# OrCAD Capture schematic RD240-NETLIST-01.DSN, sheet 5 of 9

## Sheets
5 5: size A3
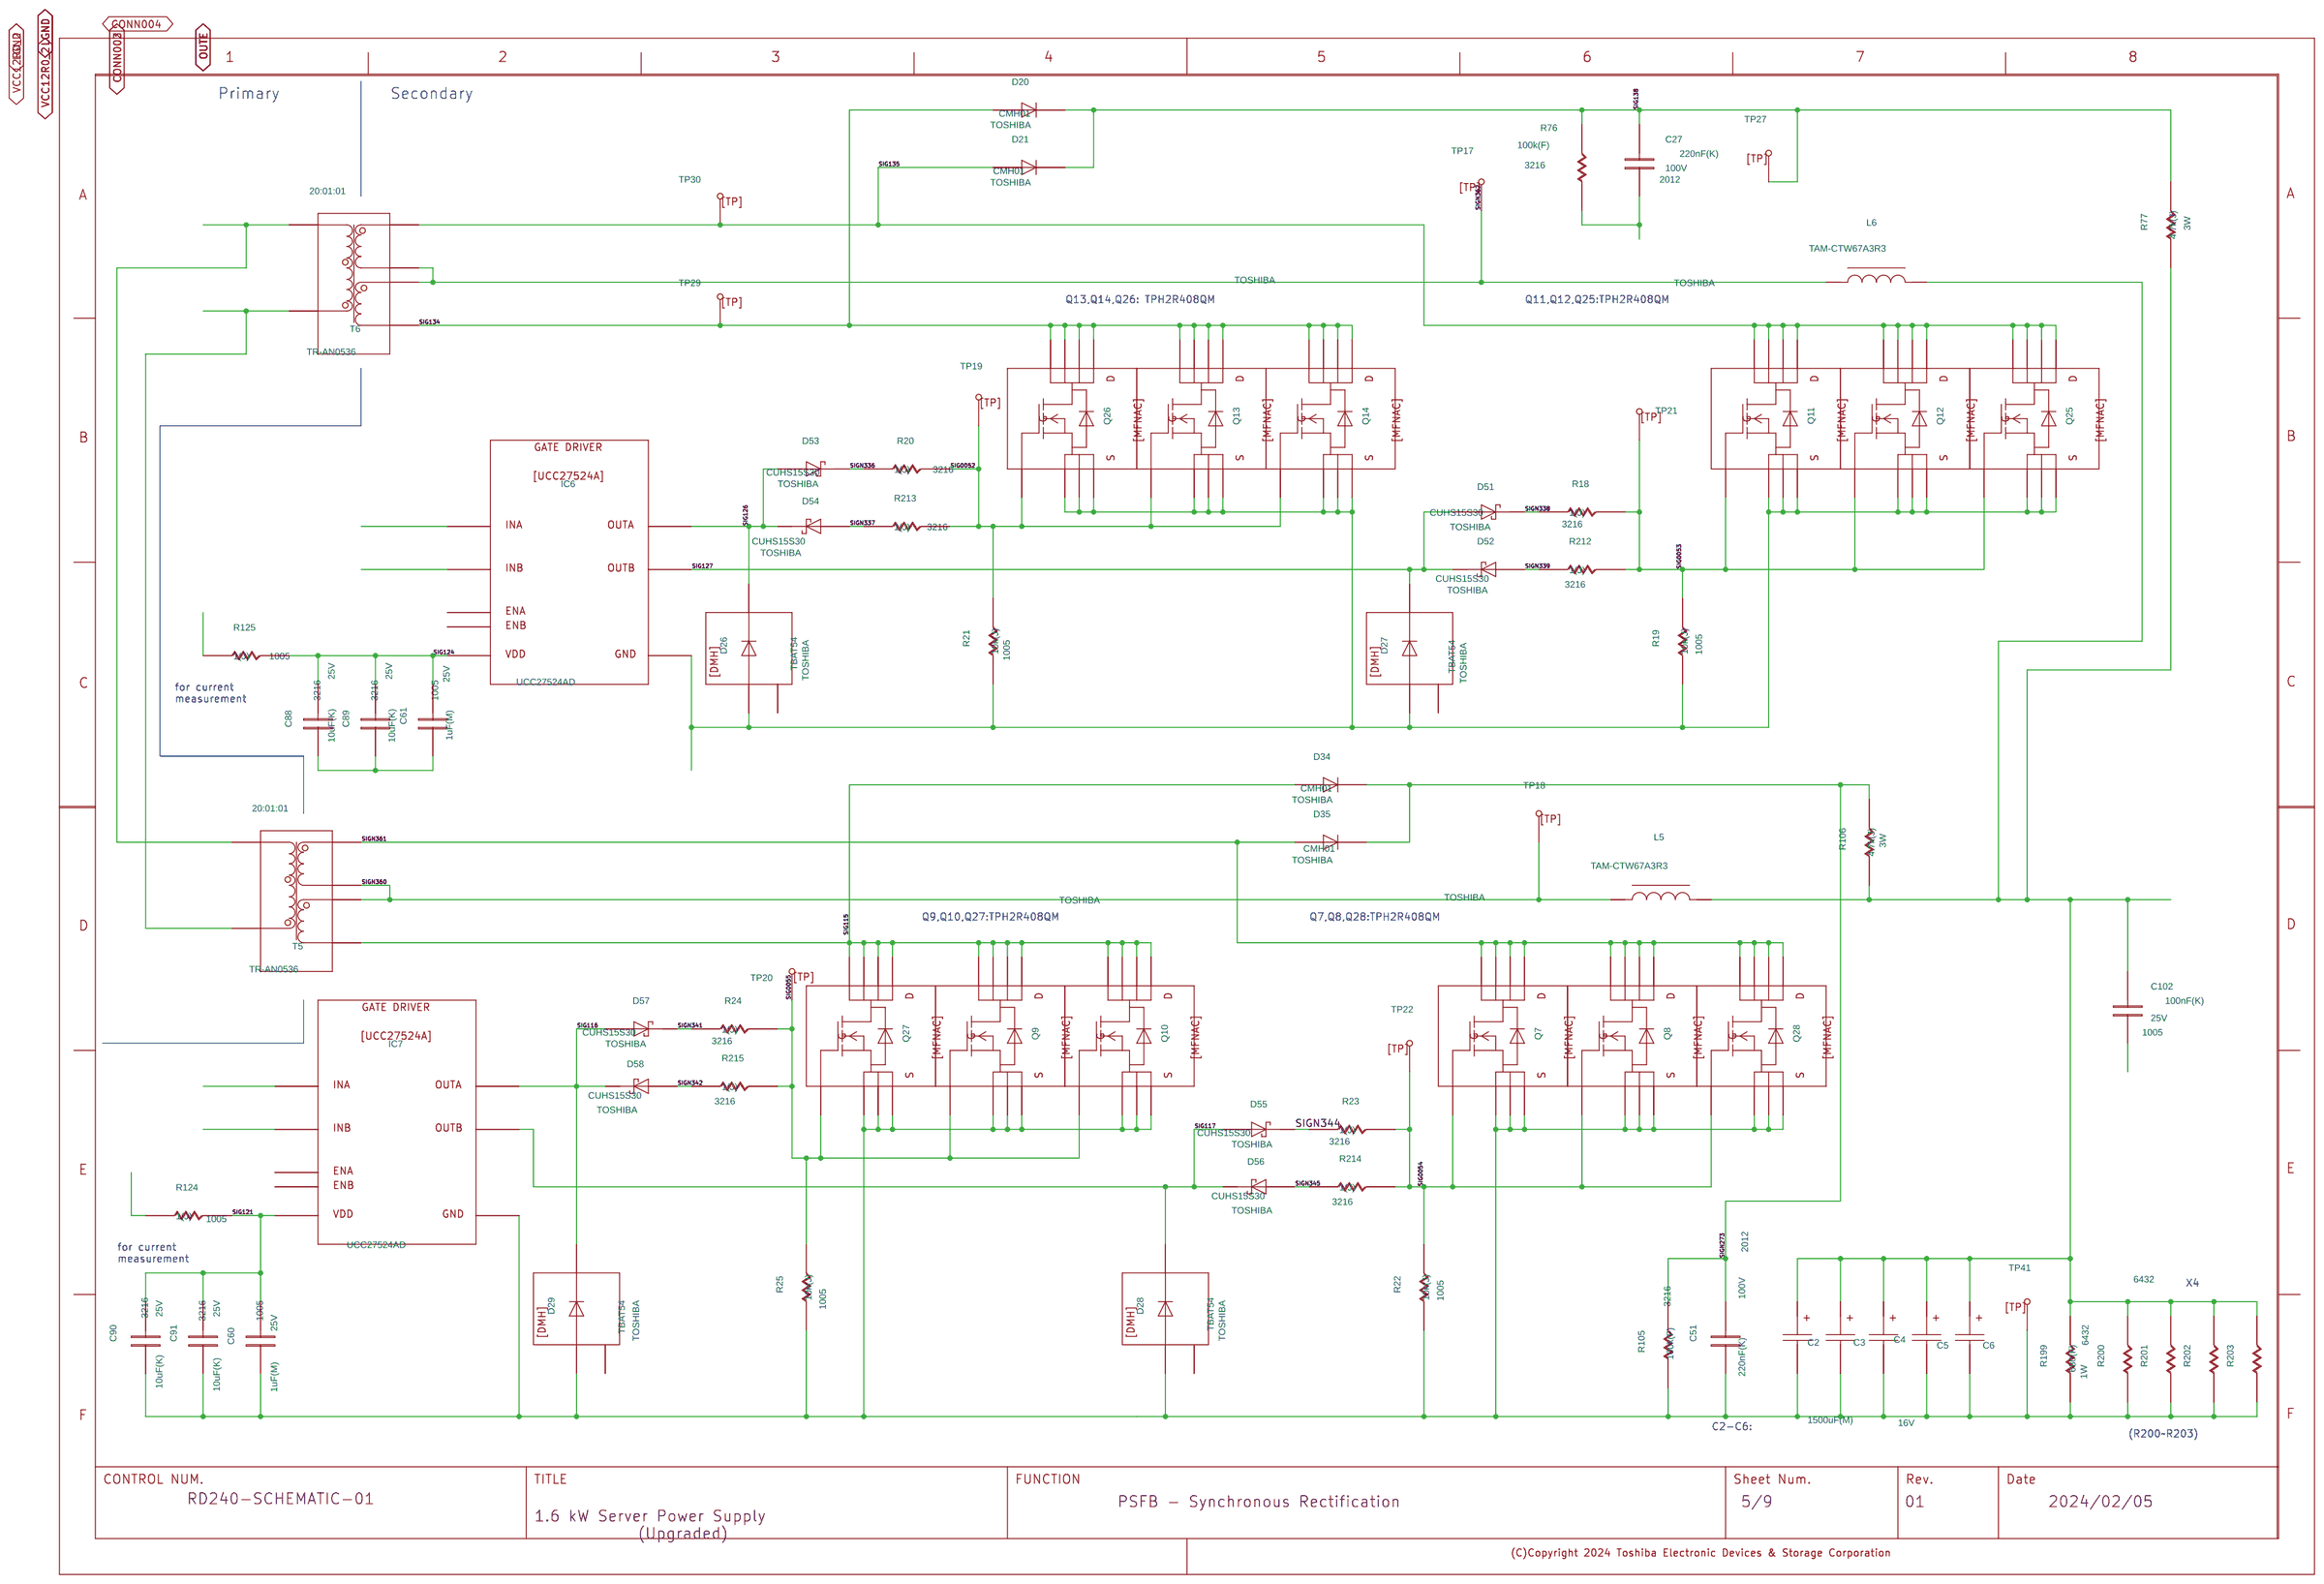
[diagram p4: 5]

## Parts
C2  CP
C3  CP
C4  CP
C5  CP
C6  CP
C27  C
C51  C
C60  C
C61  C
C88  C
C89  C
C90  C
C91  C
C102  C
D20  D
D21  D
D26  DMH
D27  DMH
D28  DMH
D29  DMH
D34  D
D35  D
D51  CUHS15S30
D52  CUHS15S30
D53  CUHS15S30
D54  CUHS15S30
D55  CUHS15S30
D56  CUHS15S30
D57  CUHS15S30
D58  CUHS15S30
IC6  L27524
IC7  L27524
L5  CTW_67A3_3UH
L6  CTW_67A3_3UH
Q7  TPH2R408QM_8PIN
Q8  TPH2R408QM_8PIN
Q9  TPH2R408QM_8PIN
Q10  TPH2R408QM_8PIN
Q11  TPH2R408QM_8PIN
Q12  TPH2R408QM_8PIN
Q13  TPH2R408QM_8PIN
Q14  TPH2R408QM_8PIN
Q25  TPH2R408QM_8PIN
Q26  TPH2R408QM_8PIN
Q27  TPH2R408QM_8PIN
Q28  TPH2R408QM_8PIN
R18  R
R19  R
R20  R
R21  R
R22  R
R23  R
R24  R
R25  R
R76  R
R77  R
R105  R
R106  R
R124  R
R125  R
R199  R
R200  R
R201  R
R202  R
R203  R
R212  R
R213  R
R214  R
R215  R
T5  T3_12V67A
T6  T3_12V67A
TP17  TP
TP18  TP
TP19  TP
TP20  TP
TP21  TP
TP22  TP
TP27  TP
TP29  TP
TP30  TP
TP41  TP
U?#4  WAKU_DEF100

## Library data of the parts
C2 = CP: AUTHOR: sptcae13; CAPACITANCETOLE: M; CDMASTERCADCELG: DC0341; CHIPSIZE: D10xL22; COMP: PRT_3; COMPONENTTYPE: 4; DATE: 2024/01/31; FNLEADFREETHET1GT2GMCTH1: 0_2_N; GCOUNT: 1; INSTANCENAME: cmp31; MAKER: RUBYCON; MAXGCOUNT: 1; NOMINALCAPACITA: 56u; OUMECLASSIFICATION: ƒAƒ‹ƒ~“d‰ðƒRƒ“ƒfƒ“ƒT; OUMEPARTTYPE: C; PMPRODUCTSTYPEG: SV1; QUADMODEL: CON_56U; RATEDVOLTAGE: 16; SIZECODESMD: DIP; TIME: 13:58:24; UPDATEDATE: 2024/01/31; UPDATETIME: 13:58:24; UPDATEUSER: sptcae13; VAL1: 1500uF(M); VAL2: 16V; VAL3: ELXZ160ELL152MJ30S
C3 = CP: AUTHOR: sptcae13; CAPACITANCETOLE: M; CHIPSIZE: D10xL22; COMP: PRT_3; COMPONENTTYPE: 4; DATE: 2024/01/31; GCOUNT: 1; INSTANCENAME: cmp32; MAKER: RUBYCON; MAXGCOUNT: 1; NOMINALCAPACITA: 56u; PMPRODUCTSTYPEG: SV1; RATEDVOLTAGE: 16; SIZECODESMD: DIP; TIME: 13:58:24; UPDATEDATE: 2024/01/31; UPDATETIME: 13:58:24; UPDATEUSER: sptcae13; VAL1: 1500uF(M); VAL2: 16V; VAL3: ELXZ160ELL152MJ30S
C4 = CP: AUTHOR: sptcae13; CAPACITANCETOLE: M; CHIPSIZE: D10xL22; COMP: PRT_3; COMPONENTTYPE: 4; DATE: 2024/01/31; GCOUNT: 1; INSTANCENAME: cmp33; MAKER: RUBYCON; MAXGCOUNT: 1; NOMINALCAPACITA: 56u; PMPRODUCTSTYPEG: SV1; RATEDVOLTAGE: 16; SIZECODESMD: DIP; TIME: 13:58:24; UPDATEDATE: 2024/01/31; UPDATETIME: 13:58:24; UPDATEUSER: sptcae13; VAL1: 1500uF(M); VAL2: 16V; VAL3: ELXZ160ELL152MJ30S
C5 = CP: AUTHOR: sptcae13; CAPACITANCETOLE: M; CHIPSIZE: D10xL22; COMP: PRT_3; COMPONENTTYPE: 4; DATE: 2024/01/31; GCOUNT: 1; INSTANCENAME: cmp34; MAKER: RUBYCON; MAXGCOUNT: 1; NOMINALCAPACITA: 56u; PMPRODUCTSTYPEG: SV1; RATEDVOLTAGE: 16; SIZECODESMD: DIP; TIME: 13:58:24; UPDATEDATE: 2024/01/31; UPDATETIME: 13:58:24; UPDATEUSER: sptcae13; VAL1: 1500uF(M); VAL2: 16V; VAL3: ELXZ160ELL152MJ30S
C6 = CP: AUTHOR: sptcae13; CAPACITANCETOLE: M; CHIPSIZE: D10xL22; COMP: PRT_3; COMPONENTTYPE: 4; DATE: 2024/01/31; GCOUNT: 1; INSTANCENAME: cmp35; MAKER: RUBYCON; MAXGCOUNT: 1; NOMINALCAPACITA: 56u; PMPRODUCTSTYPEG: SV1; RATEDVOLTAGE: 16; SIZECODESMD: DIP; TIME: 13:58:24; UPDATEDATE: 2024/01/31; UPDATETIME: 13:58:24; UPDATEUSER: sptcae13; VAL1: 1500uF(M); VAL2: 16V; VAL3: ELXZ160ELL152MJ30S
C27 = C: ADSCNVFLAG: ON; ADSCOMPONENTNAME: C_2012; ADSMODELNAME: s_GRM21AR72A224KAC5L; ALLGREEN: N:¢²¸; AUTHOR: sptcae13; CAPACITANCETOLE: K; CHIPSIZE: 1005; COMP: K0302287; COMPONENTTYPE: 4; DATE: 2024/01/31; FNAPPROVALRESUG: 5:bè(KR[h); FNCANCELLATIONG: 0:Žg—p‰Â; FNENVIRONMANTRG: N:¢²¸; FNLEADFREETHET1GT2GMCTH1: N_N_N; FUNCN: K0302287; GCOUNT: 1; ICX_PART_MODEL: CON_220N; INSTANCENAME: cmp239; MAKER: TDK; MAXGCOUNT: 1; NOMINALCAPACITA: 220n; OUMECLASSIFICATION: ƒZƒ‰ƒ~ƒbƒNƒRƒ“ƒfƒ“ƒT; OUMEMAKER: MRT ºc»ì; OUMEMAKERKATAMEI: GRM21AR72A224KAC5L; QUADMODEL: CON_220N; RATEDVOLTAGE: 100; SAVECOUNT: 0; SIZECODESMD: 2012; SQ_PART_MODEL: CON_220N; TIME: 13:58:26; UPDATEDATE: 2024/01/31; UPDATETIME: 13:58:26; UPDATEUSER: sptcae13; VAL1: 220nF(K); VAL2: 100V; VAL3: GRM21AR72A224KAC5L
C51 = C: ADSCNVFLAG: ON; ADSCOMPONENTNAME: C_2012; ADSMODELNAME: s_GRM21AR72A224KAC5L; ALLGREEN: N:¢²¸; AUTHOR: sptcae13; CAPACITANCETOLE: K; CHIPSIZE: 1005; COMP: K0302287; COMPONENTTYPE: 4; DATE: 2024/01/31; FNAPPROVALRESUG: 5:bè(KR[h); FNCANCELLATIONG: 0:Žg—p‰Â; FNENVIRONMANTRG: N:¢²¸; FNLEADFREETHET1GT2GMCTH1: N_N_N; FUNCN: K0302287; GCOUNT: 1; ICX_PART_MODEL: CON_220N; INSTANCENAME: cmp240; MAKER: TDK; MAXGCOUNT: 1; NOMINALCAPACITA: 220n; OUMECLASSIFICATION: ƒZƒ‰ƒ~ƒbƒNƒRƒ“ƒfƒ“ƒT; OUMEMAKER: MRT ºc»ì; OUMEMAKERKATAMEI: GRM21AR72A224KAC5L; QUADMODEL: CON_220N; RATEDVOLTAGE: 100; SAVECOUNT: 0; SIZECODESMD: 2012; SQ_PART_MODEL: CON_220N; TIME: 13:58:26; UPDATEDATE: 2024/01/31; UPDATETIME: 13:58:26; UPDATEUSER: sptcae13; VAL1: 220nF(K); VAL2: 100V; VAL3: GRM21AR72A224KAC5L
C60 = C: ADSMODELNAME: s_GRM155B31E105KA12D; AUTHOR: sptcae13; CAPACITANCETOLE: K; CDMASTERCADCELG: KC0005; CHIPSIZE: 1005; COMP: PRT_52; COMPONENTTYPE: 4; DATE: 2024/01/31; FNLEADFREETHET1GT2GMCTH1: 3_0_N; GCOUNT: 1; INSTANCENAME: cmp226; MAKER: TDK; MAXGCOUNT: 1; NOMINALCAPACITA: 1u; OUMECLASSIFICATION: ƒZƒ‰ƒ~ƒbƒNƒRƒ“ƒfƒ“ƒT; OUMEMAKER: MRT ºc»ì; OUMEMAKERKATAMEI: GRM155B31E105KA12D; PMPRODUCTSTYPEG: HD1; QUADMODEL: CON_1U; RATEDVOLTAGE: 25; SAVECOUNT: 0; SIZECODESMD: 1005; TEMPCHARACTERI2: B; TIME: 13:58:26; UPDATEDATE: 2024/01/31; UPDATETIME: 13:58:26; UPDATEUSER: sptcae13; VAL1: 1uF(M); VAL2: 25V; VAL3: C1005X5R1E105M050BC
C61 = C: ADSMODELNAME: s_GRM155B31E105KA12D; AUTHOR: sptcae13; CAPACITANCETOLE: K; CDMASTERCADCELG: KC0005; CHIPSIZE: 1005; COMP: PRT_52; COMPONENTTYPE: 4; DATE: 2024/01/31; FNLEADFREETHET1GT2GMCTH1: 3_0_N; GCOUNT: 1; INSTANCENAME: cmp214; MAKER: TDK; MAXGCOUNT: 1; NOMINALCAPACITA: 1u; OUMECLASSIFICATION: ƒZƒ‰ƒ~ƒbƒNƒRƒ“ƒfƒ“ƒT; OUMEMAKER: MRT ºc»ì; OUMEMAKERKATAMEI: GRM155B31E105KA12D; PMPRODUCTSTYPEG: HD1; QUADMODEL: CON_1U; RATEDVOLTAGE: 25; SAVECOUNT: 0; SIZECODESMD: 1005; TEMPCHARACTERI2: B; TIME: 13:58:26; UPDATEDATE: 2024/01/31; UPDATETIME: 13:58:26; UPDATEUSER: sptcae13; VAL1: 1uF(M); VAL2: 25V; VAL3: C1005X5R1E105M050BC
C88 = C: ADSMODELNAME: s_TMK316LD106KL_T; AUTHOR: sptcae13; CAPACITANCETOLE: K; CDMASTERCADCELG: KC0014; CHIPSIZE: 3216; COMP: PRT_46; COMPONENTTYPE: 4; DATE: 2024/01/31; FNLEADFREETHET1GT2GMCTH1: N_N_N; GCOUNT: 1; INSTANCENAME: cmp213; MAKER: TAIYO YUDEN; MAXGCOUNT: 1; NOMINALCAPACITA: 10u; OUMECLASSIFICATION: ƒZƒ‰ƒ~ƒbƒNƒRƒ“ƒfƒ“ƒT; OUMEMAKER: TYD ‘¾—z—U“d; OUMEMAKERKATAMEI: TMK316LD106KL-T; QUADMODEL: CON_10U; RATEDVOLTAGE: 25; SAVECOUNT: 0; SIZECODESMD: 3216; TIME: 13:58:26; UPDATEDATE: 2024/01/31; UPDATETIME: 13:58:26; UPDATEUSER: sptcae13; VAL1: 10uF(K); VAL2: 25V; VAL3: TMK316BJ106KL-T
C89 = C: ADSMODELNAME: s_TMK316LD106KL_T; AUTHOR: sptcae13; CAPACITANCETOLE: K; CDMASTERCADCELG: KC0014; CHIPSIZE: 3216; COMP: PRT_46; COMPONENTTYPE: 4; DATE: 2024/01/31; FNLEADFREETHET1GT2GMCTH1: N_N_N; GCOUNT: 1; INSTANCENAME: cmp212; MAKER: TAIYO YUDEN; MAXGCOUNT: 1; NOMINALCAPACITA: 10u; OUMECLASSIFICATION: ƒZƒ‰ƒ~ƒbƒNƒRƒ“ƒfƒ“ƒT; OUMEMAKER: TYD ‘¾—z—U“d; OUMEMAKERKATAMEI: TMK316LD106KL-T; QUADMODEL: CON_10U; RATEDVOLTAGE: 25; SAVECOUNT: 0; SIZECODESMD: 3216; TIME: 13:58:26; UPDATEDATE: 2024/01/31; UPDATETIME: 13:58:26; UPDATEUSER: sptcae13; VAL1: 10uF(K); VAL2: 25V; VAL3: TMK316BJ106KL-T
C90 = C: ADSMODELNAME: s_TMK316LD106KL_T; AUTHOR: sptcae13; CAPACITANCETOLE: K; CDMASTERCADCELG: KC0014; CHIPSIZE: 3216; COMP: PRT_46; COMPONENTTYPE: 4; DATE: 2024/01/31; FNLEADFREETHET1GT2GMCTH1: N_N_N; GCOUNT: 1; INSTANCENAME: cmp224; MAKER: TAIYO YUDEN; MAXGCOUNT: 1; NOMINALCAPACITA: 10u; OUMECLASSIFICATION: ƒZƒ‰ƒ~ƒbƒNƒRƒ“ƒfƒ“ƒT; OUMEMAKER: TYD ‘¾—z—U“d; OUMEMAKERKATAMEI: TMK316LD106KL-T; QUADMODEL: CON_10U; RATEDVOLTAGE: 25; SAVECOUNT: 0; SIZECODESMD: 3216; TIME: 13:58:26; UPDATEDATE: 2024/01/31; UPDATETIME: 13:58:26; UPDATEUSER: sptcae13; VAL1: 10uF(K); VAL2: 25V; VAL3: TMK316BJ106KL-T
C91 = C: ADSMODELNAME: s_TMK316LD106KL_T; AUTHOR: sptcae13; CAPACITANCETOLE: K; CDMASTERCADCELG: KC0014; CHIPSIZE: 3216; COMP: PRT_46; COMPONENTTYPE: 4; DATE: 2024/01/31; FNLEADFREETHET1GT2GMCTH1: N_N_N; GCOUNT: 1; INSTANCENAME: cmp225; MAKER: TAIYO YUDEN; MAXGCOUNT: 1; NOMINALCAPACITA: 10u; OUMECLASSIFICATION: ƒZƒ‰ƒ~ƒbƒNƒRƒ“ƒfƒ“ƒT; OUMEMAKER: TYD ‘¾—z—U“d; OUMEMAKERKATAMEI: TMK316LD106KL-T; QUADMODEL: CON_10U; RATEDVOLTAGE: 25; SAVECOUNT: 0; SIZECODESMD: 3216; TIME: 13:58:26; UPDATEDATE: 2024/01/31; UPDATETIME: 13:58:26; UPDATEUSER: sptcae13; VAL1: 10uF(K); VAL2: 25V; VAL3: TMK316BJ106KL-T
C102 = C: ADSMODELNAME: s_GRM155R71E104KE14D; AUTHOR: sptcae13; CAPACITANCETOLE: K; CDMASTERCADCELG: KC0005; CHIPSIZE: 1005; COMP: PRT_52; COMPONENTTYPE: 4; DATE: 2024/01/31; FNLEADFREETHET1GT2GMCTH1: N_N_N; GCOUNT: 1; INSTANCENAME: cmp234; MAKER: TDK; MAXGCOUNT: 1; NOMINALCAPACITA: 100n; OUMECLASSIFICATION: ƒZƒ‰ƒ~ƒbƒNƒRƒ“ƒfƒ“ƒT; OUMEMAKER: MRT ºc»ì; OUMEMAKERKATAMEI: GRM155R71E104KE14D; QUADMODEL: CON_100N; RATEDVOLTAGE: 25; SAVECOUNT: 0; SIZECODESMD: 1005; TIME: 13:58:26; UPDATEDATE: 2024/01/31; UPDATETIME: 13:58:26; UPDATEUSER: sptcae13; VAL1: 100nF(K); VAL2: 25V; VAL3: C1005X7R1E104K050BB
D20 = D: ADSMODELNAME: s_MURS340T3G@@; AUTHOR: sptcae13; CDMASTERCADCELG: KD0125; COMP: PRT_14; COMPONENTTYPE: 4; DATE: 2024/01/31; FNLEADFREETHET1GT2GMCTH1: N_N_N; FORWARDVOLTAGEM: 0; GCOUNT: 1; INSTANCENAME: cmp51; MAKER: TOSHIBA; MAXAVERAGEFORWA: 4; MAXGCOUNT: 1; MAXREPETITIVEPE: 400; MAXREVERSEVOLTA: 0; MOUNTINGFORMSMD: SMD; OUMECLASSIFICATION: êÊ®¬fq; OUMEMAKER: ONS IZ~R_N^[; OUMEMAKERKATAMEI: MURS340T3G@@; PEAKFORWARDVOLT: 1.28; PMPRODUCTSTYPEG: HEV; REVERSECURRENT: 250u; TIME: 13:58:26; UPDATEDATE: 2024/01/31; UPDATETIME: 13:58:26; UPDATEUSER: sptcae13; USERCOMPTEXT3: TOSHIBA; VAL3: CMH01; ZENERVOLTAGEMAX: 0; ZENERVOLTAGEMIN: 0
D21 = D: ADSMODELNAME: s_MURS340T3G@@; AUTHOR: sptcae13; CDMASTERCADCELG: KD0125; COMP: PRT_14; COMPONENTTYPE: 4; DATE: 2024/01/31; FNLEADFREETHET1GT2GMCTH1: N_N_N; FORWARDVOLTAGEM: 0; GCOUNT: 1; INSTANCENAME: cmp52; MAKER: TOSHIBA; MAXAVERAGEFORWA: 4; MAXGCOUNT: 1; MAXREPETITIVEPE: 400; MAXREVERSEVOLTA: 0; MOUNTINGFORMSMD: SMD; OUMECLASSIFICATION: êÊ®¬fq; OUMEMAKER: ONS IZ~R_N^[; OUMEMAKERKATAMEI: MURS340T3G@@; PEAKFORWARDVOLT: 1.28; PMPRODUCTSTYPEG: HEV; REVERSECURRENT: 250u; TIME: 13:58:26; UPDATEDATE: 2024/01/31; UPDATETIME: 13:58:26; UPDATEUSER: sptcae13; USERCOMPTEXT3: TOSHIBA; VAL3: CMH01; ZENERVOLTAGEMAX: 0; ZENERVOLTAGEMIN: 0
D26 = DMH: COMP: PRT_25; COMPONENTTYPE: 4; INSTANCENAME: cmp45; MAKER: TOSHIBA; USERCOMPTEXT3: TOSHIBA; VAL3: TBAT54
D27 = DMH: COMP: PRT_25; COMPONENTTYPE: 4; INSTANCENAME: cmp49; MAKER: TOSHIBA; USERCOMPTEXT3: TOSHIBA; VAL3: TBAT54
D28 = DMH: COMP: PRT_25; COMPONENTTYPE: 4; INSTANCENAME: cmp21; MAKER: TOSHIBA; USERCOMPTEXT3: TOSHIBA; VAL3: TBAT54
D29 = DMH: COMP: PRT_25; COMPONENTTYPE: 4; INSTANCENAME: cmp20; MAKER: TOSHIBA; USERCOMPTEXT3: TOSHIBA; VAL3: TBAT54
D34 = D: ADSMODELNAME: s_MURS340T3G@@; AUTHOR: sptcae13; CDMASTERCADCELG: KD0125; COMP: PRT_14; COMPONENTTYPE: 4; DATE: 2024/01/31; FNLEADFREETHET1GT2GMCTH1: N_N_N; FORWARDVOLTAGEM: 0; GCOUNT: 1; INSTANCENAME: cmp5; MAKER: TOSHIBA; MAXAVERAGEFORWA: 4; MAXGCOUNT: 1; MAXREPETITIVEPE: 400; MAXREVERSEVOLTA: 0; MOUNTINGFORMSMD: SMD; OUMECLASSIFICATION: êÊ®¬fq; OUMEMAKER: ONS IZ~R_N^[; OUMEMAKERKATAMEI: MURS340T3G@@; PEAKFORWARDVOLT: 1.28; PMPRODUCTSTYPEG: HEV; REVERSECURRENT: 250u; TIME: 13:58:26; UPDATEDATE: 2024/01/31; UPDATETIME: 13:58:26; UPDATEUSER: sptcae13; USERCOMPTEXT3: TOSHIBA; VAL3: CMH01; ZENERVOLTAGEMAX: 0; ZENERVOLTAGEMIN: 0
D35 = D: ADSMODELNAME: s_MURS340T3G@@; AUTHOR: sptcae13; CDMASTERCADCELG: KD0125; COMP: PRT_14; COMPONENTTYPE: 4; DATE: 2024/01/31; FNLEADFREETHET1GT2GMCTH1: N_N_N; FORWARDVOLTAGEM: 0; GCOUNT: 1; INSTANCENAME: cmp3; MAKER: TOSHIBA; MAXAVERAGEFORWA: 4; MAXGCOUNT: 1; MAXREPETITIVEPE: 400; MAXREVERSEVOLTA: 0; MOUNTINGFORMSMD: SMD; OUMECLASSIFICATION: êÊ®¬fq; OUMEMAKER: ONS IZ~R_N^[; OUMEMAKERKATAMEI: MURS340T3G@@; PEAKFORWARDVOLT: 1.28; PMPRODUCTSTYPEG: HEV; REVERSECURRENT: 250u; TIME: 13:58:26; UPDATEDATE: 2024/01/31; UPDATETIME: 13:58:26; UPDATEUSER: sptcae13; USERCOMPTEXT3: TOSHIBA; VAL3: CMH01; ZENERVOLTAGEMAX: 0; ZENERVOLTAGEMIN: 0
D51 = CUHS15S30: COMPONENTTYPE: 4; INSTANCENAME: cmp159; MAKER: TOSHIBA; USERCOMPTEXT3: TOSHIBA
D52 = CUHS15S30: COMPONENTTYPE: 4; INSTANCENAME: cmp158; MAKER: TOSHIBA; USERCOMPTEXT3: TOSHIBA
D53 = CUHS15S30: COMPONENTTYPE: 4; INSTANCENAME: cmp155; MAKER: TOSHIBA; USERCOMPTEXT3: TOSHIBA
D54 = CUHS15S30: COMPONENTTYPE: 4; INSTANCENAME: cmp154; MAKER: TOSHIBA; USERCOMPTEXT3: TOSHIBA
D55 = CUHS15S30: COMPONENTTYPE: 4; INSTANCENAME: cmp163; MAKER: TOSHIBA; USERCOMPTEXT3: TOSHIBA
D56 = CUHS15S30: COMPONENTTYPE: 4; INSTANCENAME: cmp162; MAKER: TOSHIBA; USERCOMPTEXT3: TOSHIBA
D57 = CUHS15S30: COMPONENTTYPE: 4; INSTANCENAME: cmp166; MAKER: TOSHIBA; USERCOMPTEXT3: TOSHIBA
D58 = CUHS15S30: COMPONENTTYPE: 4; INSTANCENAME: cmp165; MAKER: TOSHIBA; USERCOMPTEXT3: TOSHIBA
IC6 = L27524: COMP: PRT_63; COMPONENTTYPE: 4; INSTANCENAME: cmp37; MAKER: TEXAS; VAL3: UCC27524AD
IC7 = L27524: COMP: PRT_63; COMPONENTTYPE: 4; INSTANCENAME: cmp8; MAKER: TEXAS; VAL3: UCC27524AD
L5 = CTW_67A3_3UH: ADSMODELNAME: s_LPI_1R2D13; COMPONENTTYPE: 4; GCOUNT: 1; INDUCTANCEMAX: 0; INDUCTANCEMIN: 0; INSTANCENAME: cmp88; MAXGCOUNT: 1; MOUNTINGFORMSMD: SMD; NOMINALINDUCTA1: 1.2u; NOMINALINDUCTA2: X; VAL3: TAM-CTW67A3R3
L6 = CTW_67A3_3UH: ADSMODELNAME: s_LPI_1R2D13; COMPONENTTYPE: 4; GCOUNT: 1; INDUCTANCEMAX: 0; INDUCTANCEMIN: 0; INSTANCENAME: cmp89; MAXGCOUNT: 1; MOUNTINGFORMSMD: SMD; NOMINALINDUCTA1: 1.2u; NOMINALINDUCTA2: X; VAL3: TAM-CTW67A3R3
Q7 = TPH2R408QM_8PIN: ADSMODELNAME: s_TK040N65Z; ALLGREEN: N:¢²¸; CDMASTERCADCELG: RDP1002; COMP: TPH2R408QM(L1Q); COMPONENTTYPE: 4; FNAPPROVALRESUG: 5:bè(KR[h); FNCANCELLATIONG: 0:Žg—p‰Â; FNENVIRONMANTRG: N:¢²¸; FNLEADFREETHET1GT2GMCTH1: N_N_N; FUNCN: TPH2R408QM; GCOUNT: 1; INSTANCENAME: cmp17; MAKER: TOSHIBA; MAXCBVOLTAGE: 0; MAXCEVOLTAGE: 0; MAXCOLLECTORCUR: 0; MAXDRAINCURRENT: 57; MAXDSVOLTAGE: 650; MAXEBVOLTAGE: 0; MAXGATECURRENT: 0; MAXGCOUNT: 1; MAXGDVOLTAGE: 0; MAXGSVOLTAGE: 30; MOUNTINGFORMSMD: DIP; OUMECLASSIFICATION: Nƒ`ƒƒƒ“ƒlƒ‹MOS-FET; OUMEMAKER: TSB “ŒŽÅ; OUMEMAKERKATAMEI: TK040N65Z; OUMEPARTTYPE: Q; USERCOMPTEXT3: TOSHIBA; VAL3: TPH2R408QM
Q8 = TPH2R408QM_8PIN: ADSMODELNAME: s_TK040N65Z; ALLGREEN: N:¢²¸; CDMASTERCADCELG: RDP1002; COMP: TPH2R408QM(L1Q); COMPONENTTYPE: 4; FNAPPROVALRESUG: 5:bè(KR[h); FNCANCELLATIONG: 0:Žg—p‰Â; FNENVIRONMANTRG: N:¢²¸; FNLEADFREETHET1GT2GMCTH1: N_N_N; FUNCN: TPH2R408QM; GCOUNT: 1; INSTANCENAME: cmp16; MAKER: TOSHIBA; MAXCBVOLTAGE: 0; MAXCEVOLTAGE: 0; MAXCOLLECTORCUR: 0; MAXDRAINCURRENT: 57; MAXDSVOLTAGE: 650; MAXEBVOLTAGE: 0; MAXGATECURRENT: 0; MAXGCOUNT: 1; MAXGDVOLTAGE: 0; MAXGSVOLTAGE: 30; MOUNTINGFORMSMD: DIP; OUMECLASSIFICATION: Nƒ`ƒƒƒ“ƒlƒ‹MOS-FET; OUMEMAKER: TSB “ŒŽÅ; OUMEMAKERKATAMEI: TK040N65Z; OUMEPARTTYPE: Q; USERCOMPTEXT3: TOSHIBA; VAL3: TPH2R408QM
Q9 = TPH2R408QM_8PIN: ADSMODELNAME: s_TK040N65Z; ALLGREEN: N:¢²¸; CDMASTERCADCELG: RDP1002; COMP: TPH2R408QM(L1Q); COMPONENTTYPE: 4; FNAPPROVALRESUG: 5:bè(KR[h); FNCANCELLATIONG: 0:Žg—p‰Â; FNENVIRONMANTRG: N:¢²¸; FNLEADFREETHET1GT2GMCTH1: N_N_N; FUNCN: TPH2R408QM; GCOUNT: 1; INSTANCENAME: cmp2; MAKER: TOSHIBA; MAXCBVOLTAGE: 0; MAXCEVOLTAGE: 0; MAXCOLLECTORCUR: 0; MAXDRAINCURRENT: 57; MAXDSVOLTAGE: 650; MAXEBVOLTAGE: 0; MAXGATECURRENT: 0; MAXGCOUNT: 1; MAXGDVOLTAGE: 0; MAXGSVOLTAGE: 30; MOUNTINGFORMSMD: DIP; OUMECLASSIFICATION: Nƒ`ƒƒƒ“ƒlƒ‹MOS-FET; OUMEMAKER: TSB “ŒŽÅ; OUMEMAKERKATAMEI: TK040N65Z; OUMEPARTTYPE: Q; USERCOMPTEXT3: TOSHIBA; VAL3: TPH2R408QM
Q10 = TPH2R408QM_8PIN: ADSMODELNAME: s_TK040N65Z; ALLGREEN: N:¢²¸; CDMASTERCADCELG: RDP1002; COMP: TPH2R408QM(L1Q); COMPONENTTYPE: 4; FNAPPROVALRESUG: 5:bè(KR[h); FNCANCELLATIONG: 0:Žg—p‰Â; FNENVIRONMANTRG: N:¢²¸; FNLEADFREETHET1GT2GMCTH1: N_N_N; FUNCN: TPH2R408QM; GCOUNT: 1; INSTANCENAME: cmp11; MAKER: TOSHIBA; MAXCBVOLTAGE: 0; MAXCEVOLTAGE: 0; MAXCOLLECTORCUR: 0; MAXDRAINCURRENT: 57; MAXDSVOLTAGE: 650; MAXEBVOLTAGE: 0; MAXGATECURRENT: 0; MAXGCOUNT: 1; MAXGDVOLTAGE: 0; MAXGSVOLTAGE: 30; MOUNTINGFORMSMD: DIP; OUMECLASSIFICATION: Nƒ`ƒƒƒ“ƒlƒ‹MOS-FET; OUMEMAKER: TSB “ŒŽÅ; OUMEMAKERKATAMEI: TK040N65Z; OUMEPARTTYPE: Q; USERCOMPTEXT3: TOSHIBA; VAL3: TPH2R408QM
Q11 = TPH2R408QM_8PIN: ADSMODELNAME: s_TK040N65Z; ALLGREEN: N:¢²¸; CDMASTERCADCELG: RDP1002; COMP: TPH2R408QM(L1Q); COMPONENTTYPE: 4; FNAPPROVALRESUG: 5:bè(KR[h); FNCANCELLATIONG: 0:Žg—p‰Â; FNENVIRONMANTRG: N:¢²¸; FNLEADFREETHET1GT2GMCTH1: N_N_N; FUNCN: TPH2R408QM; GCOUNT: 1; INSTANCENAME: cmp56; MAKER: TOSHIBA; MAXCBVOLTAGE: 0; MAXCEVOLTAGE: 0; MAXCOLLECTORCUR: 0; MAXDRAINCURRENT: 57; MAXDSVOLTAGE: 650; MAXEBVOLTAGE: 0; MAXGATECURRENT: 0; MAXGCOUNT: 1; MAXGDVOLTAGE: 0; MAXGSVOLTAGE: 30; MOUNTINGFORMSMD: DIP; OUMECLASSIFICATION: Nƒ`ƒƒƒ“ƒlƒ‹MOS-FET; OUMEMAKER: TSB “ŒŽÅ; OUMEMAKERKATAMEI: TK040N65Z; OUMEPARTTYPE: Q; USERCOMPTEXT3: TOSHIBA; VAL3: TPH2R408QM
Q12 = TPH2R408QM_8PIN: ADSMODELNAME: s_TK040N65Z; ALLGREEN: N:¢²¸; CDMASTERCADCELG: RDP1002; COMP: TPH2R408QM(L1Q); COMPONENTTYPE: 4; FNAPPROVALRESUG: 5:bè(KR[h); FNCANCELLATIONG: 0:Žg—p‰Â; FNENVIRONMANTRG: N:¢²¸; FNLEADFREETHET1GT2GMCTH1: N_N_N; FUNCN: TPH2R408QM; GCOUNT: 1; INSTANCENAME: cmp55; MAKER: TOSHIBA; MAXCBVOLTAGE: 0; MAXCEVOLTAGE: 0; MAXCOLLECTORCUR: 0; MAXDRAINCURRENT: 57; MAXDSVOLTAGE: 650; MAXEBVOLTAGE: 0; MAXGATECURRENT: 0; MAXGCOUNT: 1; MAXGDVOLTAGE: 0; MAXGSVOLTAGE: 30; MOUNTINGFORMSMD: DIP; OUMECLASSIFICATION: Nƒ`ƒƒƒ“ƒlƒ‹MOS-FET; OUMEMAKER: TSB “ŒŽÅ; OUMEMAKERKATAMEI: TK040N65Z; OUMEPARTTYPE: Q; USERCOMPTEXT3: TOSHIBA; VAL3: TPH2R408QM
Q13 = TPH2R408QM_8PIN: ADSMODELNAME: s_TK040N65Z; ALLGREEN: N:¢²¸; CDMASTERCADCELG: RDP1002; COMP: TPH2R408QM(L1Q); COMPONENTTYPE: 4; FNAPPROVALRESUG: 5:bè(KR[h); FNCANCELLATIONG: 0:Žg—p‰Â; FNENVIRONMANTRG: N:¢²¸; FNLEADFREETHET1GT2GMCTH1: N_N_N; FUNCN: TPH2R408QM; GCOUNT: 1; INSTANCENAME: cmp47; MAKER: TOSHIBA; MAXCBVOLTAGE: 0; MAXCEVOLTAGE: 0; MAXCOLLECTORCUR: 0; MAXDRAINCURRENT: 57; MAXDSVOLTAGE: 650; MAXEBVOLTAGE: 0; MAXGATECURRENT: 0; MAXGCOUNT: 1; MAXGDVOLTAGE: 0; MAXGSVOLTAGE: 30; MOUNTINGFORMSMD: DIP; OUMECLASSIFICATION: Nƒ`ƒƒƒ“ƒlƒ‹MOS-FET; OUMEMAKER: TSB “ŒŽÅ; OUMEMAKERKATAMEI: TK040N65Z; OUMEPARTTYPE: Q; USERCOMPTEXT3: TOSHIBA; VAL3: TPH2R408QM
Q14 = TPH2R408QM_8PIN: ADSMODELNAME: s_TK040N65Z; ALLGREEN: N:¢²¸; CDMASTERCADCELG: RDP1002; COMP: TPH2R408QM(L1Q); COMPONENTTYPE: 4; FNAPPROVALRESUG: 5:bè(KR[h); FNCANCELLATIONG: 0:Žg—p‰Â; FNENVIRONMANTRG: N:¢²¸; FNLEADFREETHET1GT2GMCTH1: N_N_N; FUNCN: TPH2R408QM; GCOUNT: 1; INSTANCENAME: cmp46; MAKER: TOSHIBA; MAXCBVOLTAGE: 0; MAXCEVOLTAGE: 0; MAXCOLLECTORCUR: 0; MAXDRAINCURRENT: 57; MAXDSVOLTAGE: 650; MAXEBVOLTAGE: 0; MAXGATECURRENT: 0; MAXGCOUNT: 1; MAXGDVOLTAGE: 0; MAXGSVOLTAGE: 30; MOUNTINGFORMSMD: DIP; OUMECLASSIFICATION: Nƒ`ƒƒƒ“ƒlƒ‹MOS-FET; OUMEMAKER: TSB “ŒŽÅ; OUMEMAKERKATAMEI: TK040N65Z; OUMEPARTTYPE: Q; USERCOMPTEXT3: TOSHIBA; VAL3: TPH2R408QM
Q25 = TPH2R408QM_8PIN: ADSMODELNAME: s_TK040N65Z; ALLGREEN: N:¢²¸; CDMASTERCADCELG: RDP1002; COMP: TPH2R408QM(L1Q); COMPONENTTYPE: 4; FNAPPROVALRESUG: 5:bè(KR[h); FNCANCELLATIONG: 0:Žg—p‰Â; FNENVIRONMANTRG: N:¢²¸; FNLEADFREETHET1GT2GMCTH1: N_N_N; FUNCN: TPH2R408QM; GCOUNT: 1; INSTANCENAME: cmp111; MAKER: TOSHIBA; MAXCBVOLTAGE: 0; MAXCEVOLTAGE: 0; MAXCOLLECTORCUR: 0; MAXDRAINCURRENT: 57; MAXDSVOLTAGE: 650; MAXEBVOLTAGE: 0; MAXGATECURRENT: 0; MAXGCOUNT: 1; MAXGDVOLTAGE: 0; MAXGSVOLTAGE: 30; MOUNTINGFORMSMD: DIP; OUMECLASSIFICATION: Nƒ`ƒƒƒ“ƒlƒ‹MOS-FET; OUMEMAKER: TSB “ŒŽÅ; OUMEMAKERKATAMEI: TK040N65Z; OUMEPARTTYPE: Q; USERCOMPTEXT3: TOSHIBA; VAL3: TPH2R408QM
Q26 = TPH2R408QM_8PIN: ADSMODELNAME: s_TK040N65Z; ALLGREEN: N:¢²¸; CDMASTERCADCELG: RDP1002; COMP: TPH2R408QM(L1Q); COMPONENTTYPE: 4; FNAPPROVALRESUG: 5:bè(KR[h); FNCANCELLATIONG: 0:Žg—p‰Â; FNENVIRONMANTRG: N:¢²¸; FNLEADFREETHET1GT2GMCTH1: N_N_N; FUNCN: TPH2R408QM; GCOUNT: 1; INSTANCENAME: cmp112; MAKER: TOSHIBA; MAXCBVOLTAGE: 0; MAXCEVOLTAGE: 0; MAXCOLLECTORCUR: 0; MAXDRAINCURRENT: 57; MAXDSVOLTAGE: 650; MAXEBVOLTAGE: 0; MAXGATECURRENT: 0; MAXGCOUNT: 1; MAXGDVOLTAGE: 0; MAXGSVOLTAGE: 30; MOUNTINGFORMSMD: DIP; OUMECLASSIFICATION: Nƒ`ƒƒƒ“ƒlƒ‹MOS-FET; OUMEMAKER: TSB “ŒŽÅ; OUMEMAKERKATAMEI: TK040N65Z; OUMEPARTTYPE: Q; USERCOMPTEXT3: TOSHIBA; VAL3: TPH2R408QM
Q27 = TPH2R408QM_8PIN: ADSMODELNAME: s_TK040N65Z; ALLGREEN: N:¢²¸; CDMASTERCADCELG: RDP1002; COMP: TPH2R408QM(L1Q); COMPONENTTYPE: 4; FNAPPROVALRESUG: 5:bè(KR[h); FNCANCELLATIONG: 0:Žg—p‰Â; FNENVIRONMANTRG: N:¢²¸; FNLEADFREETHET1GT2GMCTH1: N_N_N; FUNCN: TPH2R408QM; GCOUNT: 1; INSTANCENAME: cmp113; MAKER: TOSHIBA; MAXCBVOLTAGE: 0; MAXCEVOLTAGE: 0; MAXCOLLECTORCUR: 0; MAXDRAINCURRENT: 57; MAXDSVOLTAGE: 650; MAXEBVOLTAGE: 0; MAXGATECURRENT: 0; MAXGCOUNT: 1; MAXGDVOLTAGE: 0; MAXGSVOLTAGE: 30; MOUNTINGFORMSMD: DIP; OUMECLASSIFICATION: Nƒ`ƒƒƒ“ƒlƒ‹MOS-FET; OUMEMAKER: TSB “ŒŽÅ; OUMEMAKERKATAMEI: TK040N65Z; OUMEPARTTYPE: Q; USERCOMPTEXT3: TOSHIBA; VAL3: TPH2R408QM
Q28 = TPH2R408QM_8PIN: ADSMODELNAME: s_TK040N65Z; ALLGREEN: N:¢²¸; CDMASTERCADCELG: RDP1002; COMP: TPH2R408QM(L1Q); COMPONENTTYPE: 4; FNAPPROVALRESUG: 5:bè(KR[h); FNCANCELLATIONG: 0:Žg—p‰Â; FNENVIRONMANTRG: N:¢²¸; FNLEADFREETHET1GT2GMCTH1: N_N_N; FUNCN: TPH2R408QM; GCOUNT: 1; INSTANCENAME: cmp115; MAKER: TOSHIBA; MAXCBVOLTAGE: 0; MAXCEVOLTAGE: 0; MAXCOLLECTORCUR: 0; MAXDRAINCURRENT: 57; MAXDSVOLTAGE: 650; MAXEBVOLTAGE: 0; MAXGATECURRENT: 0; MAXGCOUNT: 1; MAXGDVOLTAGE: 0; MAXGSVOLTAGE: 30; MOUNTINGFORMSMD: DIP; OUMECLASSIFICATION: Nƒ`ƒƒƒ“ƒlƒ‹MOS-FET; OUMEMAKER: TSB “ŒŽÅ; OUMEMAKERKATAMEI: TK040N65Z; OUMEPARTTYPE: Q; USERCOMPTEXT3: TOSHIBA; VAL3: TPH2R408QM
R18 = R: ADSMODELNAME: s_ERJ8GEYJ3R3V; CDMASTERCADCELG: KC0014; CHIPSIZE: 3216; COMPONENTTYPE: 4; FNLEADFREETHET1GT2GMCTH1: N_N_N; GCOUNT: 1; INSTANCENAME: cmp208; MAKER: VISHAY; MAXGCOUNT: 1; MOUNTINGFORMSMD: SMD; NOMINALRESISTAN: 3.3; OUMECLASSIFICATION: \ÊÀpÅèïRí; OUMEMAKER: NAE pi\jbNGNgjbNfoCX; OUMEMAKERKATAMEI: ERJ8GEYJ3R3V; POWERRATING: 250m; QUADMODEL: RES_3.3; RESISTANCETOLER: J; SAVECOUNT: 0; SIZECODESMD: 3216; VAL1: 1(J); VAL2: 250mW; VAL3: RK73B2BTTD1R0J
R19 = R: ADSMODELNAME: s_RC0402FR_071KL; ALLGREEN: 0:O[; CDMASTERCADCELG: KC0005; CHIPSIZE: 1608; COMPONENTTYPE: 4; FNAPPROVALRESUG: B:i(GREEN); FNCANCELLATIONG: 0:Žg—p‰Â; FNENVIRONMANTRG: 1:gpL(K§ÎÛO); FNLEADFREETHET1GT2GMCTH1: 2_2_N; GANSWERREV: 8; GCOUNT: 1; INSTANCENAME: cmp210; MAKER: KOA; MAXGCOUNT: 1; MOUNTINGFORMSMD: SMD; NOMINALRESISTAN: 1K; OUMECLASSIFICATION: \ÊÀpÅèïRí; OUMEMAKER: YGO ƒ„ƒQƒI; OUMEMAKERKATAMEI: RC0402FR-071KL; PMPRODUCTSTYPEG: HD1; POWERRATING: 63m; QUADMODEL: RES_1K; RESISTANCETOLER: F; SAVECOUNT: 0; SIZECODESMD: 1005; VAL1: 10k(J); VAL2: 63mW; VAL3: RK73B1ERTTP103J
R20 = R: ADSMODELNAME: s_ERJ8GEYJ3R3V; CDMASTERCADCELG: KC0014; CHIPSIZE: 3216; COMPONENTTYPE: 4; FNLEADFREETHET1GT2GMCTH1: N_N_N; GCOUNT: 1; INSTANCENAME: cmp207; MAKER: VISHAY; MAXGCOUNT: 1; MOUNTINGFORMSMD: SMD; NOMINALRESISTAN: 3.3; OUMECLASSIFICATION: \ÊÀpÅèïRí; OUMEMAKER: NAE pi\jbNGNgjbNfoCX; OUMEMAKERKATAMEI: ERJ8GEYJ3R3V; POWERRATING: 250m; QUADMODEL: RES_3.3; RESISTANCETOLER: J; SAVECOUNT: 0; SIZECODESMD: 3216; VAL1: 1(J); VAL2: 250mW; VAL3: RK73B2BTTD1R0J
R21 = R: ADSMODELNAME: s_RC0402FR_071KL; ALLGREEN: 0:O[; CDMASTERCADCELG: KC0005; CHIPSIZE: 1608; COMPONENTTYPE: 4; FNAPPROVALRESUG: B:i(GREEN); FNCANCELLATIONG: 0:Žg—p‰Â; FNENVIRONMANTRG: 1:gpL(K§ÎÛO); FNLEADFREETHET1GT2GMCTH1: 2_2_N; GANSWERREV: 8; GCOUNT: 1; INSTANCENAME: cmp211; MAKER: KOA; MAXGCOUNT: 1; MOUNTINGFORMSMD: SMD; NOMINALRESISTAN: 1K; OUMECLASSIFICATION: \ÊÀpÅèïRí; OUMEMAKER: YGO ƒ„ƒQƒI; OUMEMAKERKATAMEI: RC0402FR-071KL; PMPRODUCTSTYPEG: HD1; POWERRATING: 63m; QUADMODEL: RES_1K; RESISTANCETOLER: F; SAVECOUNT: 0; SIZECODESMD: 1005; VAL1: 10k(J); VAL2: 63mW; VAL3: RK73B1ERTTP103J
R22 = R: ADSMODELNAME: s_RC0402FR_071KL; ALLGREEN: 0:O[; CDMASTERCADCELG: KC0005; CHIPSIZE: 1608; COMPONENTTYPE: 4; FNAPPROVALRESUG: B:i(GREEN); FNCANCELLATIONG: 0:Žg—p‰Â; FNENVIRONMANTRG: 1:gpL(K§ÎÛO); FNLEADFREETHET1GT2GMCTH1: 2_2_N; GANSWERREV: 8; GCOUNT: 1; INSTANCENAME: cmp228; MAKER: KOA; MAXGCOUNT: 1; MOUNTINGFORMSMD: SMD; NOMINALRESISTAN: 1K; OUMECLASSIFICATION: \ÊÀpÅèïRí; OUMEMAKER: YGO ƒ„ƒQƒI; OUMEMAKERKATAMEI: RC0402FR-071KL; PMPRODUCTSTYPEG: HD1; POWERRATING: 63m; QUADMODEL: RES_1K; RESISTANCETOLER: F; SAVECOUNT: 0; SIZECODESMD: 1005; VAL1: 10k(J); VAL2: 63mW; VAL3: RK73B1ERTTP103J
R23 = R: ADSMODELNAME: s_ERJ8GEYJ3R3V; CDMASTERCADCELG: KC0014; CHIPSIZE: 3216; COMPONENTTYPE: 4; FNLEADFREETHET1GT2GMCTH1: N_N_N; GCOUNT: 1; INSTANCENAME: cmp229; MAKER: VISHAY; MAXGCOUNT: 1; MOUNTINGFORMSMD: SMD; NOMINALRESISTAN: 3.3; OUMECLASSIFICATION: \ÊÀpÅèïRí; OUMEMAKER: NAE pi\jbNGNgjbNfoCX; OUMEMAKERKATAMEI: ERJ8GEYJ3R3V; POWERRATING: 250m; QUADMODEL: RES_3.3; RESISTANCETOLER: J; SAVECOUNT: 0; SIZECODESMD: 3216; VAL1: 1(J); VAL2: 250mW; VAL3: RK73B2BTTD1R0J
R24 = R: ADSMODELNAME: s_ERJ8GEYJ3R3V; CDMASTERCADCELG: KC0014; CHIPSIZE: 3216; COMPONENTTYPE: 4; FNLEADFREETHET1GT2GMCTH1: N_N_N; GCOUNT: 1; INSTANCENAME: cmp222; MAKER: VISHAY; MAXGCOUNT: 1; MOUNTINGFORMSMD: SMD; NOMINALRESISTAN: 3.3; OUMECLASSIFICATION: \ÊÀpÅèïRí; OUMEMAKER: NAE pi\jbNGNgjbNfoCX; OUMEMAKERKATAMEI: ERJ8GEYJ3R3V; POWERRATING: 250m; QUADMODEL: RES_3.3; RESISTANCETOLER: J; SAVECOUNT: 0; SIZECODESMD: 3216; VAL1: 1(J); VAL2: 250mW; VAL3: RK73B2BTTD1R0J
R25 = R: ADSMODELNAME: s_RC0402FR_071KL; ALLGREEN: 0:O[; CDMASTERCADCELG: KC0005; CHIPSIZE: 1608; COMPONENTTYPE: 4; FNAPPROVALRESUG: B:i(GREEN); FNCANCELLATIONG: 0:Žg—p‰Â; FNENVIRONMANTRG: 1:gpL(K§ÎÛO); FNLEADFREETHET1GT2GMCTH1: 2_2_N; GANSWERREV: 8; GCOUNT: 1; INSTANCENAME: cmp227; MAKER: KOA; MAXGCOUNT: 1; MOUNTINGFORMSMD: SMD; NOMINALRESISTAN: 1K; OUMECLASSIFICATION: \ÊÀpÅèïRí; OUMEMAKER: YGO ƒ„ƒQƒI; OUMEMAKERKATAMEI: RC0402FR-071KL; PMPRODUCTSTYPEG: HD1; POWERRATING: 63m; QUADMODEL: RES_1K; RESISTANCETOLER: F; SAVECOUNT: 0; SIZECODESMD: 1005; VAL1: 10k(J); VAL2: 63mW; VAL3: RK73B1ERTTP103J
R76 = R: ADSCOMPONENTNAME: R_3216; ADSMODELNAME: s_RK73H2BTTD1003F@@; CHIPSIZE: 3216; COMP: PRT_5; COMPONENTTYPE: 4; GCOUNT: 1; INSTANCENAME: cmp99; MAKER: PANASONIC; MAXGCOUNT: 1; MOUNTINGFORMSMD: SMD; PMPRODUCTSTYPEG: DA; SAVECOUNT: 0; SIZECODESMD: 3216; VAL1: 100k(F); VAL2: 250mW; VAL3: ERJ-8ENF1003V
R77 = R: CDMASTERCADCELG: AXK0015; COMP: PRT_54; COMPONENTTYPE: 4; FNLEADFREETHET1GT2GMCTH1: N_N_N; GCOUNT: 1; INSTANCENAME: cmp100; MAKER: VISHAY; MAXGCOUNT: 1; MOUNTINGFORMSMD: DIP; NOMINALRESISTAN: 100; OUMECLASSIFICATION: _»à®çÅèïRí; OUMEMAKER: KOA R[A; OUMEMAKERKATAMEI: MOS3CT521A101J@@; PMPRODUCTSTYPEG: HEV; POWERRATING: 3; QUADMODEL: RES_100; RESISTANCETOLER: J; SAVECOUNT: 0; SIZECODESMD: DIP; VAL1: 4.7k(J); VAL2: 3W; VAL3: PR03000204701JAC00
R105 = R: ADSCOMPONENTNAME: R_3216; ADSMODELNAME: s_RK73H2BTTD1003F@@; CHIPSIZE: 3216; COMP: PRT_5; COMPONENTTYPE: 4; GCOUNT: 1; INSTANCENAME: cmp90; MAKER: PANASONIC; MAXGCOUNT: 1; MOUNTINGFORMSMD: SMD; PMPRODUCTSTYPEG: DA; SAVECOUNT: 0; SIZECODESMD: 3216; VAL1: 100k(F); VAL2: 250mW; VAL3: ERJ-8ENF1003V
R106 = R: CDMASTERCADCELG: AXK0015; COMP: PRT_54; COMPONENTTYPE: 4; FNLEADFREETHET1GT2GMCTH1: N_N_N; GCOUNT: 1; INSTANCENAME: cmp92; MAKER: VISHAY; MAXGCOUNT: 1; MOUNTINGFORMSMD: DIP; NOMINALRESISTAN: 100; OUMECLASSIFICATION: _»à®çÅèïRí; OUMEMAKER: KOA R[A; OUMEMAKERKATAMEI: MOS3CT521A101J@@; PMPRODUCTSTYPEG: HEV; POWERRATING: 3; QUADMODEL: RES_100; RESISTANCETOLER: J; SAVECOUNT: 0; SIZECODESMD: DIP; VAL1: 4.7k(J); VAL2: 3W; VAL3: PR03000204701JAC00
R124 = R: ADSMODELNAME: s_RC0402FR_071KL; ALLGREEN: 0:O[; CDMASTERCADCELG: KC0005; CHIPSIZE: 1608; COMPONENTTYPE: 4; FNAPPROVALRESUG: B:i(GREEN); FNCANCELLATIONG: 0:Žg—p‰Â; FNENVIRONMANTRG: 1:gpL(K§ÎÛO); FNLEADFREETHET1GT2GMCTH1: 2_2_N; GANSWERREV: 8; GCOUNT: 1; INSTANCENAME: cmp81; MAKER: PANASONIC; MAXGCOUNT: 1; MOUNTINGFORMSMD: SMD; NOMINALRESISTAN: 1K; OUMECLASSIFICATION: \ÊÀpÅèïRí; OUMEMAKER: YGO ƒ„ƒQƒI; OUMEMAKERKATAMEI: RC0402FR-071KL; PMPRODUCTSTYPEG: HD1; POWERRATING: 63m; QUADMODEL: RES_1K; RESISTANCETOLER: F; SAVECOUNT: 0; SIZECODESMD: 1005; VAL1: 1(J); VAL2: 63mW; VAL3: ERJ2GEJ1R0X
R125 = R: ADSMODELNAME: s_RC0402FR_071KL; ALLGREEN: 0:O[; CDMASTERCADCELG: KC0005; CHIPSIZE: 1608; COMPONENTTYPE: 4; FNAPPROVALRESUG: B:i(GREEN); FNCANCELLATIONG: 0:Žg—p‰Â; FNENVIRONMANTRG: 1:gpL(K§ÎÛO); FNLEADFREETHET1GT2GMCTH1: 2_2_N; GANSWERREV: 8; GCOUNT: 1; INSTANCENAME: cmp104; MAKER: PANASONIC; MAXGCOUNT: 1; MOUNTINGFORMSMD: SMD; NOMINALRESISTAN: 1K; OUMECLASSIFICATION: \ÊÀpÅèïRí; OUMEMAKER: YGO ƒ„ƒQƒI; OUMEMAKERKATAMEI: RC0402FR-071KL; PMPRODUCTSTYPEG: HD1; POWERRATING: 63m; QUADMODEL: RES_1K; RESISTANCETOLER: F; SAVECOUNT: 0; SIZECODESMD: 1005; VAL1: 1(J); VAL2: 63mW; VAL3: ERJ2GEJ1R0X
R199 = R: CHIPSIZE: 6432; COMP: PRT_43; COMPONENTTYPE: 4; GCOUNT: 1; INSTANCENAME: cmp116; MAKER: VISHAY; MAXGCOUNT: 1; MOUNTINGFORMSMD: DIP; PMPRODUCTSTYPEG: HEV; SAVECOUNT: 0; SIZECODESMD: 6432; VAL1: 680(F); VAL2: 1W; VAL3: CRCW2512680RFKEG
R200 = R: CHIPSIZE: 6432; COMP: PRT_43; COMPONENTTYPE: 4; GCOUNT: 1; INSTANCENAME: cmp121; MAKER: VISHAY; MAXGCOUNT: 1; MOUNTINGFORMSMD: DIP; NOTMOUNT: NOT MOUNT; PMPRODUCTSTYPEG: HEV; SAVECOUNT: 0; SIZECODESMD: 6432; VAL1: 680(F); VAL2: 1W; VAL3: CRCW2512680RFKEG
R201 = R: CHIPSIZE: 6432; COMP: PRT_43; COMPONENTTYPE: 4; GCOUNT: 1; INSTANCENAME: cmp122; MAKER: VISHAY; MAXGCOUNT: 1; MOUNTINGFORMSMD: DIP; NOTMOUNT: NOT MOUNT; PMPRODUCTSTYPEG: HEV; SAVECOUNT: 0; SIZECODESMD: 6432; VAL1: 680(F); VAL2: 1W; VAL3: CRCW2512680RFKEG
R202 = R: CHIPSIZE: 6432; COMP: PRT_43; COMPONENTTYPE: 4; GCOUNT: 1; INSTANCENAME: cmp123; MAKER: VISHAY; MAXGCOUNT: 1; MOUNTINGFORMSMD: DIP; NOTMOUNT: NOT MOUNT; PMPRODUCTSTYPEG: HEV; SAVECOUNT: 0; SIZECODESMD: 6432; VAL1: 680(F); VAL2: 1W; VAL3: CRCW2512680RFKEG
R203 = R: CHIPSIZE: 6432; COMP: PRT_43; COMPONENTTYPE: 4; GCOUNT: 1; INSTANCENAME: cmp124; MAKER: VISHAY; MAXGCOUNT: 1; MOUNTINGFORMSMD: DIP; NOTMOUNT: NOT MOUNT; PMPRODUCTSTYPEG: HEV; SAVECOUNT: 0; SIZECODESMD: 6432; VAL1: 680(F); VAL2: 1W; VAL3: CRCW2512680RFKEG
R212 = R: ADSMODELNAME: s_ERJ8GEYJ3R3V; CDMASTERCADCELG: KC0014; CHIPSIZE: 3216; COMPONENTTYPE: 4; FNLEADFREETHET1GT2GMCTH1: N_N_N; GCOUNT: 1; INSTANCENAME: cmp209; MAKER: VISHAY; MAXGCOUNT: 1; MOUNTINGFORMSMD: SMD; NOMINALRESISTAN: 3.3; OUMECLASSIFICATION: \ÊÀpÅèïRí; OUMEMAKER: NAE pi\jbNGNgjbNfoCX; OUMEMAKERKATAMEI: ERJ8GEYJ3R3V; POWERRATING: 250m; QUADMODEL: RES_3.3; RESISTANCETOLER: J; SAVECOUNT: 0; SIZECODESMD: 3216; VAL1: 1(J); VAL2: 250mW; VAL3: RK73B2BTTD1R0J
R213 = R: ADSMODELNAME: s_ERJ8GEYJ3R3V; CDMASTERCADCELG: KC0014; CHIPSIZE: 3216; COMPONENTTYPE: 4; FNLEADFREETHET1GT2GMCTH1: N_N_N; GCOUNT: 1; INSTANCENAME: cmp206; MAKER: VISHAY; MAXGCOUNT: 1; MOUNTINGFORMSMD: SMD; NOMINALRESISTAN: 3.3; OUMECLASSIFICATION: \ÊÀpÅèïRí; OUMEMAKER: NAE pi\jbNGNgjbNfoCX; OUMEMAKERKATAMEI: ERJ8GEYJ3R3V; POWERRATING: 250m; QUADMODEL: RES_3.3; RESISTANCETOLER: J; SAVECOUNT: 0; SIZECODESMD: 3216; VAL1: 1(J); VAL2: 250mW; VAL3: RK73B2BTTD1R0J
R214 = R: ADSMODELNAME: s_ERJ8GEYJ3R3V; CDMASTERCADCELG: KC0014; CHIPSIZE: 3216; COMPONENTTYPE: 4; FNLEADFREETHET1GT2GMCTH1: N_N_N; GCOUNT: 1; INSTANCENAME: cmp230; MAKER: VISHAY; MAXGCOUNT: 1; MOUNTINGFORMSMD: SMD; NOMINALRESISTAN: 3.3; OUMECLASSIFICATION: \ÊÀpÅèïRí; OUMEMAKER: NAE pi\jbNGNgjbNfoCX; OUMEMAKERKATAMEI: ERJ8GEYJ3R3V; POWERRATING: 250m; QUADMODEL: RES_3.3; RESISTANCETOLER: J; SAVECOUNT: 0; SIZECODESMD: 3216; VAL1: 1(J); VAL2: 250mW; VAL3: RK73B2BTTD1R0J
R215 = R: ADSMODELNAME: s_ERJ8GEYJ3R3V; CDMASTERCADCELG: KC0014; CHIPSIZE: 3216; COMPONENTTYPE: 4; FNLEADFREETHET1GT2GMCTH1: N_N_N; GCOUNT: 1; INSTANCENAME: cmp223; MAKER: VISHAY; MAXGCOUNT: 1; MOUNTINGFORMSMD: SMD; NOMINALRESISTAN: 3.3; OUMECLASSIFICATION: \ÊÀpÅèïRí; OUMEMAKER: NAE pi\jbNGNgjbNfoCX; OUMEMAKERKATAMEI: ERJ8GEYJ3R3V; POWERRATING: 250m; QUADMODEL: RES_3.3; RESISTANCETOLER: J; SAVECOUNT: 0; SIZECODESMD: 3216; VAL1: 1(J); VAL2: 250mW; VAL3: RK73B2BTTD1R0J
T5 T6 = T3_12V67A: COMPONENTTYPE: 4; VAL1: 20:01:01; VAL3: TR-AN0536
TP17 = TP: AUTHOR: sptcae13; COMP: PRT_44; COMPONENTKIND: 127; COMPONENTTYPE: 4; DATE: 2024/01/31; INSTANCENAME: cmp174; MAKER: MAC8; TIME: 13:58:25; UPDATEDATE: 2024/01/31; UPDATETIME: 13:58:25; UPDATEUSER: sptcae13; VAL3: HK-2-S
TP18 = TP: AUTHOR: sptcae13; COMP: PRT_44; COMPONENTTYPE: 4; DATE: 2024/01/31; INSTANCENAME: cmp175; MAKER: MAC8; TIME: 13:58:25; UPDATEDATE: 2024/01/31; UPDATETIME: 13:58:25; UPDATEUSER: sptcae13; VAL3: HK-2-S
TP19 = TP: AUTHOR: sptcae13; COMP: PRT_44; COMPONENTTYPE: 4; DATE: 2024/01/31; INSTANCENAME: cmp176; MAKER: MAC8; TIME: 13:58:25; UPDATEDATE: 2024/01/31; UPDATETIME: 13:58:25; UPDATEUSER: sptcae13; VAL3: HK-2-S
TP20 = TP: AUTHOR: sptcae13; COMP: PRT_44; COMPONENTTYPE: 4; DATE: 2024/01/31; INSTANCENAME: cmp177; MAKER: MAC8; TIME: 13:58:25; UPDATEDATE: 2024/01/31; UPDATETIME: 13:58:25; UPDATEUSER: sptcae13; VAL3: HK-2-S
TP21 = TP: AUTHOR: sptcae13; COMP: PRT_44; COMPONENTTYPE: 4; DATE: 2024/01/31; INSTANCENAME: cmp178; MAKER: MAC8; TIME: 13:58:25; UPDATEDATE: 2024/01/31; UPDATETIME: 13:58:25; UPDATEUSER: sptcae13; VAL3: HK-2-S
TP22 = TP: AUTHOR: sptcae13; COMP: PRT_44; COMPONENTTYPE: 4; DATE: 2024/01/31; INSTANCENAME: cmp179; MAKER: MAC8; TIME: 13:58:25; UPDATEDATE: 2024/01/31; UPDATETIME: 13:58:25; UPDATEUSER: sptcae13; VAL3: HK-2-S
TP27 = TP: AUTHOR: sptcae13; COMP: PRT_44; COMPONENTKIND: 127; COMPONENTTYPE: 4; DATE: 2024/01/31; INSTANCENAME: cmp184; MAKER: MAC8; TIME: 13:58:25; UPDATEDATE: 2024/01/31; UPDATETIME: 13:58:25; UPDATEUSER: sptcae13; VAL3: HK-2-S
TP29 = TP: AUTHOR: sptcae13; COMP: PRT_44; COMPONENTTYPE: 4; DATE: 2024/01/31; INSTANCENAME: cmp186; MAKER: MAC8; TIME: 13:58:25; UPDATEDATE: 2024/01/31; UPDATETIME: 13:58:25; UPDATEUSER: sptcae13; VAL3: HK-2-S
TP30 = TP: AUTHOR: sptcae13; COMP: PRT_44; COMPONENTTYPE: 4; DATE: 2024/01/31; INSTANCENAME: cmp187; MAKER: MAC8; TIME: 13:58:25; UPDATEDATE: 2024/01/31; UPDATETIME: 13:58:25; UPDATEUSER: sptcae13; VAL3: HK-2-S
TP41 = TP: AUTHOR: sptcae13; COMP: PRT_34; COMPONENTTYPE: 4; DATE: 2024/01/31; INSTANCENAME: cmp190; MAKER: MAC8; TIME: 13:58:25; UPDATEDATE: 2024/01/31; UPDATETIME: 13:58:25; UPDATEUSER: sptcae13; VAL3: LC-22-S-BLACK
U?#4 = WAKU_DEF100: COMPONENTTYPE: 2; DATE: 2024/02/05; DESIGNED: TOSHIBA; DRAWINGNUMBER: RD240-SCHEMATIC-01; FUNCTION: PSFB - Synchronous Rectification; INSTANCENAME: cmp237; PAGENUMBER: 5; REVISION: 01; SHEETNUMBER: 5/9; SHTSAVECOUNT: 60; TITLE: 1.6 kW Server Power Supply / (Upgraded); UPDATEDATE: 2024/02/07; UPDATETIME: 10:55:43; UPDATEUSER: t5459927

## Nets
VCC12R0_2: R124.1 R125.1 ; also on sheet 2 4
CONN002: T5.1 T6.1 ; also on sheet 6
CONN003: T5.2 T6.2 ; also on sheet 6
CONN004: C2.2 C3.2 C4.2 C5.2 C6.2 C102.2 L5.F L6.F R77.1 R106.1 R199.2 R200.2 R201.2 R202.2 R203.2 ; also on sheet 1 4
LGND: C2.1 C3.1 C4.1 C5.1 C6.1 C27.1 C51.1 C60.1 C61.1 C88.1 C89.1 C90.1 C91.1 C102.1 D26.A D27.A D28.A D29.A IC6.3 IC7.3 Q7.1 Q7.2 Q7.3 Q8.1 Q8.2 Q8.3 Q9.1 Q9.2 Q9.3 Q10.1 Q10.2 Q10.3 Q11.1 Q11.2 Q11.3 Q12.1 Q12.2 Q12.3 Q13.1 Q13.2 Q13.3 Q14.1 Q14.2 Q14.3 Q25.1 Q25.2 Q25.3 Q26.1 Q26.2 Q26.3 Q27.1 Q27.2 Q27.3 Q28.1 Q28.2 Q28.3 R19.1 R21.1 R22.1 R25.1 R76.1 R105.1 R199.1 R200.1 R201.1 R202.1 R203.1 TP41.1 ; also on sheet 1 2 3 4 6 9
OUTE: IC6.2 IC7.2 ; also on sheet 4
OUTF: IC6.4 IC7.4 ; also on sheet 4
SIG0052: Q13.4 Q14.4 Q26.4 R20.2 R21.2 R213.2 TP19.1
SIG0053: Q11.4 Q12.4 Q25.4 R18.2 R19.2 R212.2 TP21.1
SIG0054: Q7.4 Q8.4 Q28.4 R22.2 R23.2 R214.2 TP22.1
SIG0055: Q9.4 Q10.4 Q27.4 R24.2 R25.2 R215.2 TP20.1
SIG115: D34.A Q9.5 Q9.6 Q9.7 Q9.8 Q10.5 Q10.6 Q10.7 Q10.8 Q27.5 Q27.6 Q27.7 Q27.8 T5.5
SIG116: D29.C D57.A D58.C IC7.7
SIG117: D28.C D55.A D56.C IC7.5
SIG121: C60.2 C90.2 C91.2 IC7.6 R124.2
SIG124: C61.2 C88.2 C89.2 IC6.6 R125.2
SIG126: D26.C D53.A D54.C IC6.7
SIG127: D27.C D51.A D52.C IC6.5
SIG134: D20.A Q13.5 Q13.6 Q13.7 Q13.8 Q14.5 Q14.6 Q14.7 Q14.8 Q26.5 Q26.6 Q26.7 Q26.8 T6.5 TP29.1
SIG135: D21.A Q11.5 Q11.6 Q11.7 Q11.8 Q12.5 Q12.6 Q12.7 Q12.8 Q25.5 Q25.6 Q25.7 Q25.8 T6.6 TP30.1
SIG138: C27.2 D20.C D21.C R76.2 R77.2 TP27.1
SIGN273: C51.2 D34.C D35.C R105.2 R106.2
SIGN336: D53.C R20.1
SIGN337: D54.A R213.1
SIGN338: D51.C R18.1
SIGN339: D52.A R212.1
SIGN341: D57.C R24.1
SIGN342: D58.A R215.1
SIGN344: D55.C R23.1
SIGN345: D56.A R214.1
SIGN360: L5.S T5.3 T5.4 TP18.1
SIGN361: D35.A Q7.5 Q7.6 Q7.7 Q7.8 Q8.5 Q8.6 Q8.7 Q8.8 Q28.5 Q28.6 Q28.7 Q28.8 T5.6
SIGN362: L6.S T6.3 T6.4 TP17.1

Not connected (* = marked no-connect by the designer): D26 NC; D27 NC; D28 NC; D29 NC; IC6 1 8; IC7 1 8

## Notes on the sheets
sheet 5
- Primary
- Secondary
- Q13,Q14,Q26: TPH2R408QM
- Q11,Q12,Q25:TPH2R408QM
- for current
  measurement
- Q9,Q10,Q27:TPH2R408QM
- Q7,Q8,Q28:TPH2R408QM
- for current
  measurement
- X4
- C2-C6:
- (R200~R203)
